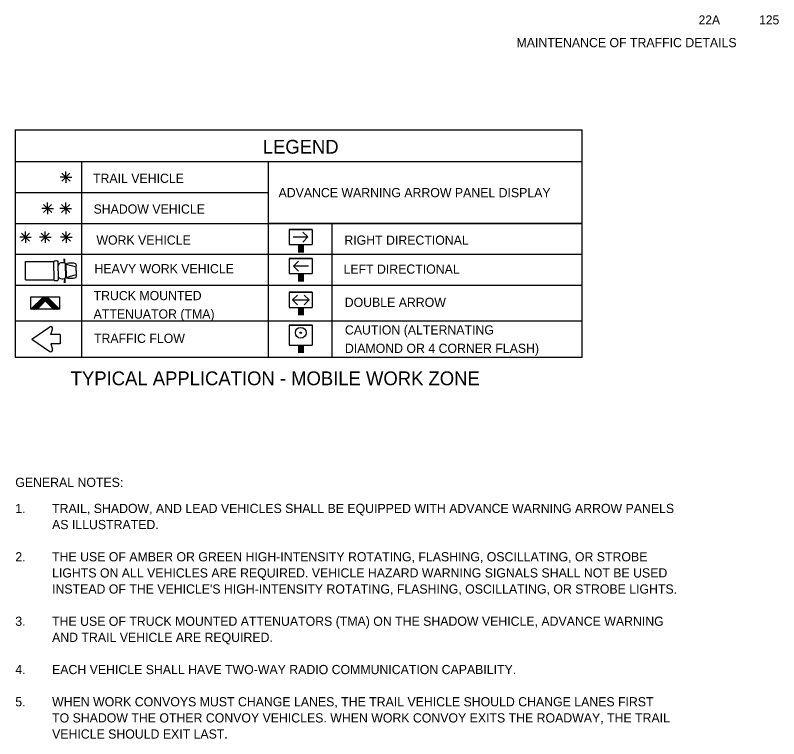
# Model space of a CAD drawing. Extents: x -747 to 834, y -5485 to -3577.
# Drawn here: x 335.6 to 833.6, y -4953 to -4481.5 of the extents above; entities that cross this region are included whole.
import ezdxf

# ---------------------------------------------------------------- set-up
doc = ezdxf.new("R2010")
doc.units = 0
doc.layers.add('R_Border', color=7, linetype='Continuous')
doc.layers.add('Working Level 1', color=7, linetype='Continuous')

msp = doc.modelspace()

# ---------------------------------------------------------------- linework, layer by layer
at = {"layer": 'Working Level 1'}
for p, q in [((335.63, -4556.11), (335.63, -4704.33)), ((335.63, -4556.11), (705.31, -4556.11)), ((705.31, -4704.33), (705.31, -4556.11)), ((335.63, -4576.92), (705.31, -4576.92)), ((378.91, -4576.57), (378.91, -4704.33)), ((378.91, -4576.57), (378.91, -4704.33)), ((500.68, -4576.92), (500.68, -4704.33)), ((368.7, -4587.06), (366.04, -4584.4)), ((368.63, -4587.11), (371.3, -4584.45)), ((368.7, -4587.06), (368.7, -4583.3)), ((368.7, -4587.06), (364.93, -4587.06)), ((368.7, -4587.06), (366.04, -4589.72)), ((368.7, -4587.06), (371.36, -4589.72)), ((368.7, -4587.06), (368.7, -4590.82)), ((368.7, -4587.06), (372.46, -4587.06)), ((335.63, -4597.03), (500.68, -4597.03)), ((356.72, -4607.39), (354.06, -4604.73)), ((356.67, -4607.45), (359.34, -4604.79)), ((356.72, -4607.39), (356.72, -4603.63)), ((368.55, -4607.39), (365.89, -4604.73)), ((368.5, -4607.44), (371.16, -4604.78)), ((368.55, -4607.39), (368.55, -4603.63)), ((356.72, -4607.39), (352.96, -4607.39)), ((356.72, -4607.39), (354.07, -4610.05)), ((356.72, -4607.39), (359.39, -4610.05)), ((356.72, -4607.39), (356.72, -4611.15)), ((356.72, -4607.39), (360.49, -4607.39)), ((368.55, -4607.39), (364.79, -4607.39)), ((368.55, -4607.39), (365.89, -4610.05)), ((368.55, -4607.39), (371.21, -4610.05)), ((368.55, -4607.39), (368.55, -4611.15)), ((368.55, -4607.39), (372.31, -4607.39)), ((335.63, -4617.13), (705.31, -4617.13)), ((705.31, -4617.13), (500.68, -4617.13)), ((514.31, -4621.03), (514.31, -4630.98)), ((529.36, -4621.03), (514.31, -4621.03)), ((514.31, -4621.03), (529.36, -4621.03)), ((529.36, -4621.03), (529.36, -4630.98)), ((542.05, -4617.13), (542.05, -4704.33)), ((342.31, -4626.13), (338.55, -4626.13)), ((342.31, -4626.13), (339.65, -4623.47)), ((342.31, -4626.13), (339.65, -4628.79)), ((342.26, -4626.19), (344.92, -4623.52)), ((342.31, -4626.13), (342.31, -4622.37)), ((342.31, -4626.13), (344.97, -4628.79)), ((342.31, -4626.13), (342.31, -4629.89)), ((342.31, -4626.13), (346.08, -4626.13)), ((355.21, -4626.13), (351.44, -4626.13)), ((355.21, -4626.13), (352.54, -4623.47)), ((355.21, -4626.13), (352.54, -4628.79)), ((355.15, -4626.19), (357.81, -4623.52)), ((355.21, -4626.13), (355.21, -4622.37)), ((355.21, -4626.13), (357.86, -4628.79)), ((355.21, -4626.13), (355.21, -4629.89)), ((355.21, -4626.13), (358.97, -4626.13)), ((368.94, -4626.13), (365.18, -4626.13)), ((368.94, -4626.13), (366.28, -4623.47)), ((368.94, -4626.13), (366.28, -4628.79)), ((368.89, -4626.19), (371.55, -4623.52)), ((368.94, -4626.13), (368.94, -4622.37)), ((368.94, -4626.13), (371.61, -4628.79)), ((368.94, -4626.13), (368.94, -4629.89)), ((368.94, -4626.13), (372.7, -4626.13)), ((516.86, -4626), (526.49, -4626)), ((526.49, -4626), (523.22, -4629.28)), ((526.49, -4626), (523.29, -4622.81)), ((514.31, -4630.98), (529.36, -4630.98)), ((520.33, -4630.98), (520.33, -4636.05)), ((521.08, -4630.98), (521.08, -4636.05)), ((521.83, -4630.98), (521.83, -4636.05)), ((522.59, -4630.98), (522.59, -4636.05)), ((523.34, -4630.98), (523.34, -4636.05)), ((335.63, -4637.24), (705.31, -4637.24)), ((335.63, -4637.24), (500.61, -4637.24)), ((367.53, -4641.65), (367.53, -4640.19)), ((367.77, -4643.06), (367.77, -4640.19)), ((367.96, -4643.06), (367.96, -4640.19)), ((514.31, -4639.97), (514.31, -4649.91)), ((529.36, -4639.97), (514.31, -4639.97)), ((514.31, -4639.97), (529.36, -4639.97)), ((529.36, -4639.97), (529.36, -4649.91)), ((342.31, -4642), (360.86, -4642)), ((342.31, -4654), (342.31, -4642)), ((360.86, -4648), (360.86, -4642)), ((363.71, -4648), (363.71, -4642)), ((368.48, -4648), (368.48, -4643.69)), ((368.86, -4643.69), (375.35, -4645.45)), ((368.86, -4648), (368.86, -4643.69)), ((375.35, -4648), (375.35, -4645.45)), ((517.18, -4644.94), (520.38, -4641.75)), ((526.81, -4644.94), (517.18, -4644.94)), ((517.18, -4644.94), (520.45, -4648.21)), ((360.86, -4648), (360.86, -4654)), ((363.71, -4648), (363.71, -4654)), ((368.48, -4648), (368.48, -4652.32)), ((368.86, -4648), (368.86, -4652.32)), ((368.86, -4652.32), (375.35, -4650.55)), ((375.35, -4648), (375.35, -4650.55)), ((514.31, -4649.91), (529.36, -4649.91)), ((520.33, -4649.91), (520.33, -4654.99)), ((521.08, -4649.91), (521.08, -4654.99)), ((521.83, -4649.91), (521.83, -4654.99)), ((522.59, -4649.91), (522.59, -4654.99)), ((523.34, -4649.91), (523.34, -4654.99)), ((342.31, -4654), (360.86, -4654)), ((367.53, -4654.35), (367.53, -4655.83)), ((367.77, -4652.95), (367.77, -4655.83)), ((367.96, -4652.95), (367.96, -4655.83)), ((335.63, -4657.35), (705.31, -4657.35)), ((345.82, -4673.08), (353.94, -4664.96)), ((364.46, -4673.02), (356.43, -4665)), ((514.31, -4662.05), (514.31, -4672)), ((529.36, -4662.05), (514.31, -4662.05)), ((514.31, -4662.05), (529.36, -4662.05)), ((516.42, -4667.03), (519.62, -4663.84)), ((527.24, -4667.03), (524.04, -4663.84)), ((529.36, -4662.05), (529.36, -4672)), ((349.88, -4673.08), (355.21, -4667.72)), ((360.56, -4673.08), (355.21, -4667.72)), ((516.42, -4667.03), (519.7, -4670.3)), ((517.18, -4667.03), (526.49, -4667.03)), ((527.24, -4667.03), (523.97, -4670.3)), ((514.31, -4672), (529.36, -4672)), ((520.33, -4672), (520.33, -4677.07)), ((521.08, -4672), (521.08, -4677.07)), ((521.83, -4672), (521.83, -4677.07)), ((522.59, -4672), (522.59, -4677.07)), ((523.34, -4672), (523.34, -4677.07)), ((335.63, -4680.72), (705.31, -4680.72)), ((346.51, -4692.59), (358.14, -4684.61)), ((514.31, -4683.46), (514.31, -4696.41)), ((529.36, -4683.46), (514.31, -4683.46)), ((514.31, -4683.46), (529.36, -4683.46)), ((529.36, -4683.46), (529.36, -4696.41)), ((358.87, -4689.54), (360.01, -4686.01)), ((364.93, -4689.54), (358.87, -4689.54)), ((364.93, -4689.54), (364.93, -4695.64)), ((346.51, -4692.59), (358.14, -4700.56)), ((364.93, -4695.64), (358.87, -4695.64)), ((358.87, -4695.64), (360.01, -4699.17)), ((514.31, -4696.41), (529.36, -4696.41)), ((520.33, -4696.41), (520.33, -4701.48)), ((521.08, -4696.41), (521.08, -4701.48)), ((521.83, -4696.41), (521.83, -4701.48)), ((522.59, -4696.41), (522.59, -4701.48)), ((523.34, -4696.41), (523.34, -4701.48)), ((335.63, -4704.33), (705.31, -4704.33))]:
    msp.add_line(p, q, dxfattribs=at)
msp.add_lwpolyline([(364.46, -4664.93), (364.46, -4673.08), (345.82, -4673.08), (345.82, -4664.93)], close=True, dxfattribs=at)
for points in [[(347.24, -4671.66), (357.28, -4665.86)], [(348.24, -4670.66), (357.01, -4665.59)], [(349.24, -4669.66), (356.75, -4665.32)], [(350.24, -4668.65), (356.48, -4665.05)], [(351.24, -4667.65), (355.86, -4664.99)], [(352.25, -4666.65), (355.13, -4664.98)], [(353.24, -4665.65), (354.43, -4664.97)], [(346.24, -4672.66), (357.55, -4666.13)], [(346.26, -4673.08), (354.8, -4668.15)], [(346.99, -4673.08), (353.85, -4669.12)], [(347.73, -4673.08), (352.89, -4670.1)], [(355.32, -4667.84), (357.82, -4666.4)], [(355.59, -4668.11), (358.08, -4666.67)], [(355.87, -4668.37), (358.35, -4666.94)], [(356.13, -4668.65), (358.62, -4667.21)], [(356.4, -4668.92), (358.89, -4667.48)], [(356.67, -4669.19), (359.16, -4667.75)], [(356.94, -4669.45), (359.43, -4668.02)], [(357.2, -4669.72), (359.69, -4668.28)], [(357.48, -4669.99), (359.96, -4668.56)], [(357.74, -4670.26), (360.23, -4668.82)], [(358.01, -4670.53), (360.5, -4669.09)], [(358.28, -4670.8), (360.77, -4669.36)], [(358.55, -4671.07), (361.03, -4669.63)], [(358.82, -4671.34), (361.3, -4669.91)], [(359.09, -4671.6), (361.57, -4670.17)], [(359.36, -4671.87), (361.84, -4670.44)], [(359.62, -4672.14), (362.11, -4670.71)], [(359.9, -4672.42), (362.37, -4670.98)], [(348.46, -4673.08), (351.93, -4671.07)], [(349.2, -4673.08), (350.97, -4672.05)], [(349.93, -4673.08), (350.02, -4673.02)], [(360.16, -4672.68), (362.64, -4671.25)], [(360.43, -4672.95), (362.9, -4671.52)], [(360.95, -4673.08), (363.18, -4671.79)], [(361.69, -4673.08), (363.45, -4672.05)], [(362.43, -4673.08), (363.72, -4672.33)], [(363.16, -4673.08), (363.99, -4672.6)], [(363.89, -4673.08), (364.25, -4672.87)]]:
    msp.add_lwpolyline(points, dxfattribs=at)
for radius in [3.51, 0.437]:
    msp.add_circle((521.83, -4688.43), radius, dxfattribs=at)
for centre, radius, start, end in [((373.77, -4644.61), 1.8, 331.8801, 28.1199), ((373.77, -4651.39), 1.8, 331.8801, 28.1199), ((358.84, -4685.63), 1.23, 342.1824, 124.4455), ((358.84, -4699.55), 1.23, 235.5546, 17.8176)]:
    msp.add_arc(centre, radius, start, end, dxfattribs=at)
for centre, major_axis, ratio, start_param, end_param in [((362.29, -4642.01), (1.42, 0), 0.269913, 0, 3.141593), ((366.09, -4643.98), (2.38, 0.29), 0.503092, 0, 3.141593), ((372.11, -4643.72), (3.24, -0.04), 0.2034, 0, 3.141593), ((362.29, -4653.99), (1.42, 0), 0.269913, 3.141593, 6.283185), ((366.09, -4652.02), (2.38, -0.29), 0.503092, 3.141593, 6.283185), ((372.11, -4652.28), (3.24, 0.04), 0.2034, 3.141593, 6.283185)]:
    msp.add_ellipse(centre, major_axis=major_axis, ratio=ratio, start_param=start_param, end_param=end_param, dxfattribs=at)

# ---------------------------------------------------------------- texts
at = {"layer": 'R_Border'}
for s, height, p in [('22A', 5.862, (781.37, -4487.46)), ('125', 5.862, (820.86, -4487.46)), ('MAINTENANCE OF TRAFFIC DETAILS', 6, (662.59, -4502.31))]:
    msp.add_text(s, height=height, dxfattribs=at).set_placement(p)
at = {"layer": 'Working Level 1'}
for s, height, p in [('LEGEND', 9, (497.05, -4571.71)), ('TRAIL VEHICLE', 6, (386.34, -4590.76)), ('ADVANCE WARNING ARROW PANEL DISPLAY', 6, (507.37, -4600.1)), ('SHADOW VEHICLE', 6, (386.69, -4610.8)), ('WORK VEHICLE', 6, (388.56, -4631.02)), ('RIGHT DIRECTIONAL', 6, (550.29, -4631.06)), ('HEAVY WORK VEHICLE', 6, (387.3, -4649.66)), ('LEFT DIRECTIONAL', 6, (549.73, -4649.95)), ('TRUCK MOUNTED ', 6, (386.73, -4667.19)), ('DOUBLE ARROW', 6, (550.53, -4671.58)), ('ATTENUATOR (TMA)', 6, (386.73, -4679.19)), ('CAUTION (ALTERNATING ', 6, (550.67, -4689.57)), ('TRAFFIC FLOW', 6, (386.99, -4695.06)), ('DIAMOND OR 4 CORNER FLASH)', 6, (550.67, -4701.57)), ('TYPICAL APPLICATION - MOBILE WORK ZONE', 9, (371.79, -4722.62)), ('GENERAL NOTES:', 6, (335.65, -4788.92)), ('1. ', 6, (335.65, -4805.93)), ('TRAIL, SHADOW, AND LEAD VEHICLES SHALL BE EQUIPPED WITH ADVANCE WARNING ARROW PANELS', 6, (359.65, -4805.93)), ('AS ILLUSTRATED. ', 6, (359.65, -4816.43)), ('2.', 6, (335.65, -4837.43)), ('THE USE OF AMBER OR GREEN HIGH-INTENSITY ROTATING, FLASHING, OSCILLATING, OR STROBE ', 6, (359.65, -4837.43)), ('LIGHTS ON ALL VEHICLES ARE REQUIRED. VEHICLE HAZARD WARNING SIGNALS SHALL NOT BE USED ', 6, (359.65, -4847.93)), ("INSTEAD OF THE VEHICLE'S HIGH-INTENSITY ROTATING, FLASHING, OSCILLATING, OR STROBE LIGHTS.", 6, (359.65, -4858.43)), ('3. ', 6, (335.65, -4879.43)), ('THE USE OF TRUCK MOUNTED ATTENUATORS (TMA) ON THE SHADOW VEHICLE, ADVANCE WARNING', 6, (359.65, -4879.43)), ('AND TRAIL VEHICLE ARE REQUIRED.', 6, (359.65, -4889.93)), ('4. ', 6, (335.65, -4910.93)), ('EACH VEHICLE SHALL HAVE TWO-WAY RADIO COMMUNICATION CAPABILITY. ', 6, (359.65, -4910.93)), ('5. ', 6, (335.65, -4931.93)), ('WHEN WORK CONVOYS MUST CHANGE LANES, THE TRAIL VEHICLE SHOULD CHANGE LANES FIRST ', 6, (359.65, -4931.93)), ('TO SHADOW THE OTHER CONVOY VEHICLES. WHEN WORK CONVOY EXITS THE ROADWAY, THE TRAIL', 6, (359.65, -4942.43)), ('VEHICLE SHOULD EXIT LAST.', 6, (359.65, -4952.93))]:
    msp.add_text(s, height=height, dxfattribs=at).set_placement(p)

doc.saveas('drawing.dxf')
